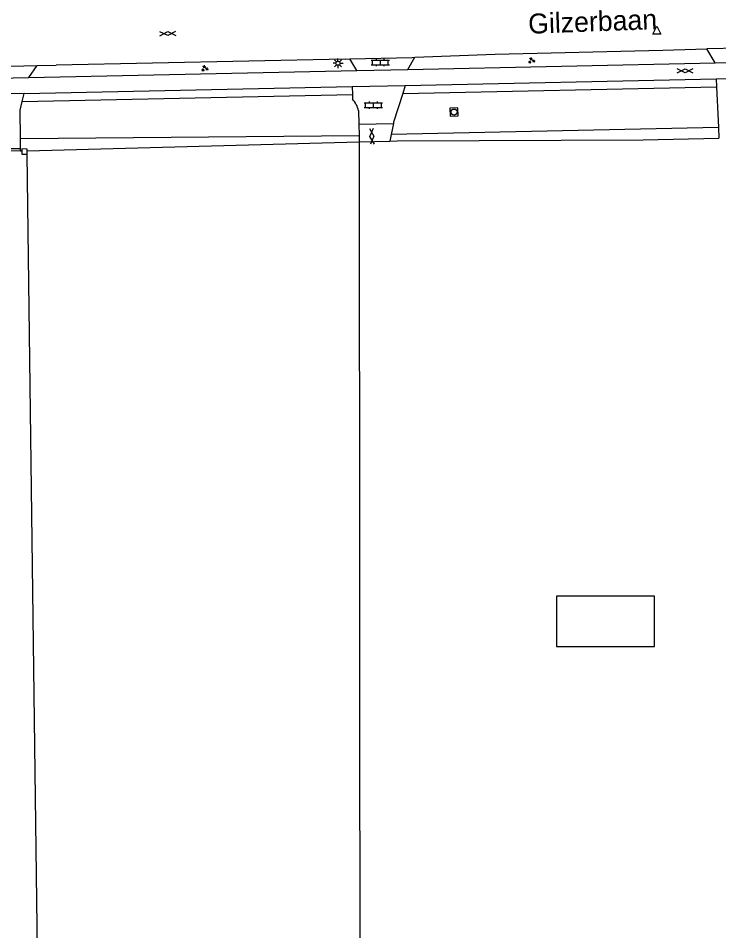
# Model space of a CAD drawing. Extents: x 128999 to 131010, y 395498 to 399007.
# Drawn here: x 130694.9 to 130782.7, y 396021.6 to 396136.1 of the extents above; entities that cross this region are included whole.
import ezdxf

# ---------------------------------------------------------------- set-up
doc = ezdxf.new("R2010")
doc.units = 0
for name, color, linetype in [('gg-afsc-erfafscheiding', 7, 'Continuous'), ('gg-afsc-hekwerk', 7, 'Continuous'), ('gg-afsc-muur', 7, 'Continuous'), ('gg-anno-openbare ruimte label', 7, 'Continuous'), ('gg-knt-verharding', 7, 'Continuous'), ('gt-bbg-plantopografie pand', 7, 'Continuous'), ('gt-grn-groengrens', 7, 'Continuous'), ('gt-grn-groengrens NZ', 7, 'Continuous'), ('gt-grn-vlakafsluiter', 7, 'Continuous'), ('gt-grn-weggrens', 7, 'Continuous'), ('gt-symb-gesloten verharding', 7, 'Continuous'), ('gt-symb-groenvak', 7, 'Continuous'), ('gt-symb-klinker verharding', 7, 'Continuous'), ('gt-symb-lichtmast', 7, 'Continuous'), ('gt-symb-rioolschacht', 7, 'Continuous'), ('gt-symb-waterafsluiter', 7, 'Continuous')]:
    doc.layers.add(name, color=color, linetype=linetype)

# ---------------------------------------------------------------- blocks, each defined once
blk = doc.blocks.new('gt0-GRVAK')
at = {"layer": 'gt-symb-groenvak'}
for p, q in [((-0.11, 0.19), (-0.23, 0.24)), ((-0.18, 0.15), (0.09, 0.15)), ((-0.09, 0.21), (-0.16, 0.32)), ((-0.05, 0.21), (-0.05, 0.39)), ((0, 0.21), (0.06, 0.32)), ((0.01, 0.19), (0.13, 0.24)), ((0.26, -0.05), (0.2, 0.06)), ((0.31, -0.05), (0.31, 0.13)), ((0.35, -0.05), (0.41, 0.06)), ((-0.24, -0.23), (-0.36, -0.18)), ((-0.32, -0.26), (-0.05, -0.26)), ((-0.23, -0.21), (-0.29, -0.1)), ((-0.18, -0.2), (-0.18, -0.02)), ((-0.14, -0.21), (-0.07, -0.1)), ((-0.12, -0.23), (0, -0.18)), ((0.24, -0.07), (0.12, -0.02)), ((0.17, -0.11), (0.44, -0.11)), ((0.37, -0.07), (0.49, -0.02))]:
    blk.add_line(p, q, dxfattribs=at)
blk = doc.blocks.new('gt0-WAFSL')
at = {"layer": 'gt-symb-waterafsluiter'}
for p, q in [((-0.5, -0.33), (0, 0.67)), ((0, 0.67), (0.5, -0.33)), ((0.5, -0.33), (-0.5, -0.33))]:
    blk.add_line(p, q, dxfattribs=at)
blk = doc.blocks.new('gt0-GESVH1')
at = {"layer": 'gt-symb-gesloten verharding'}
for p, q in [((-0.99, -0.26), (0.01, 0.24)), ((0.01, -0.26), (-0.99, 0.24)), ((0.01, 0.24), (1.01, -0.26)), ((1.01, 0.24), (0.01, -0.26))]:
    blk.add_line(p, q, dxfattribs=at)
blk = doc.blocks.new('gt0-KL1')
at = {"layer": 'gt-symb-klinker verharding'}
for p, q in [((-1.15, 0.3), (1.15, 0.3)), ((-1, -0.3), (-1, 0.3)), ((-0.5, 0.3), (-0.5, 0.45)), ((0, -0.3), (0, 0.3)), ((0.5, 0.3), (0.5, 0.45)), ((1, -0.3), (1, 0.3)), ((-1.15, -0.3), (1.15, -0.3)), ((-0.5, -0.45), (-0.5, -0.3)), ((0.5, -0.45), (0.5, -0.3))]:
    blk.add_line(p, q, dxfattribs=at)
blk = doc.blocks.new('gt0-RS')
at = {"layer": 'gt-symb-rioolschacht'}
blk.add_lwpolyline([(-0.5, -0.5), (0.5, -0.5), (0.5, 0.5), (-0.5, 0.5)], close=True, dxfattribs=at)
blk.add_circle((0, 0), 0.375, dxfattribs=at)
blk = doc.blocks.new('gt0-LMAST')
at = {"layer": 'gt-symb-lichtmast'}
for p, q in [((-0.18, 0.17), (-0.45, 0.44)), ((-0.01, 0.25), (-0.01, 0.62)), ((0.17, 0.17), (0.44, 0.44)), ((-0.26, 0), (-0.63, 0)), ((-0.18, -0.18), (-0.45, -0.45)), ((-0.01, -0.25), (-0.01, -0.63)), ((0.44, -0.45), (0.17, -0.18)), ((0.24, 0), (0.62, 0))]:
    blk.add_line(p, q, dxfattribs=at)
blk.add_circle((-0.01, 0), 0.25, dxfattribs=at)

msp = doc.modelspace()

# ---------------------------------------------------------------- linework, layer by layer
at = {"layer": 'gg-afsc-erfafscheiding'}
msp.add_lwpolyline([(130742.42, 396120.7), (130773.27, 396120.84), (130782.76, 396121.07)], dxfattribs=at)
at = {"layer": 'gg-afsc-hekwerk'}
for p, q in [((130691.73, 396119.52), (130695.18, 396119.47)), ((130695.18, 396119.47), (130695.36, 396119.47))]:
    msp.add_line(p, q, dxfattribs=at)
at = {"layer": 'gg-afsc-muur'}
msp.add_line((130696.01, 396119.03), (130696.03, 396119.48), dxfattribs=at)
for points in [[(130695.36, 396119.47), (130695.35, 396119.05), (130696.01, 396119.03)], [(130696.03, 396119.48), (130696.03, 396119.69), (130695.37, 396119.71), (130695.36, 396119.47)]]:
    msp.add_lwpolyline(points, dxfattribs=at)
at = {"layer": 'gg-knt-verharding'}
for p, q in [((130788.9, 396132.43), (130781.24, 396132.25)), ((130775.71, 396132.09), (130781.24, 396132.25)), ((130782.3, 396130.51), (130781.24, 396132.25)), ((130689.55, 396130), (130697.27, 396130.16)), ((130696.22, 396128.66), (130697.27, 396130.16)), ((130697.27, 396130.16), (130699.66, 396130.22)), ((130735.88, 396130.97), (130699.66, 396130.22)), ((130735.88, 396130.97), (130736.48, 396130.99)), ((130736.48, 396130.99), (130744.3, 396131.18)), ((130737.35, 396129.54), (130736.48, 396130.99)), ((130743.73, 396129.68), (130744.61, 396131.19)), ((130743.73, 396129.68), (130782.3, 396130.51)), ((130744.3, 396131.18), (130744.61, 396131.19)), ((130782.3, 396130.51), (130788.12, 396130.66)), ((130696.22, 396128.66), (130737.35, 396129.54)), ((130737.35, 396129.54), (130743.73, 396129.68)), ((130690.65, 396128.56), (130696.22, 396128.66)), ((130743.41, 396127.67), (130782.4, 396128.5)), ((130782.4, 396128.5), (130787.95, 396128.65)), ((130782.4, 396128.5), (130782.45, 396127.5)), ((130695.65, 396126.66), (130736.78, 396127.53)), ((130736.78, 396127.53), (130743.41, 396127.67)), ((130736.78, 396127.53), (130736.8, 396126.53)), ((130743.41, 396127.67), (130743.1, 396126.67)), ((130782.45, 396127.5), (130782.7, 396122.39)), ((130695.65, 396126.66), (130691.26, 396126.57)), ((130695.41, 396125.66), (130695.65, 396126.66)), ((130736.8, 396126.53), (130736.81, 396125.95)), ((130737.55, 396124.5), (130737.59, 396122.81)), ((130737.59, 396122.81), (130741.93, 396122.89)), ((130737.59, 396122.81), (130737.63, 396121.39)), ((130741.93, 396122.89), (130741.67, 396121.53)), ((130782.7, 396122.39), (130782.76, 396121.07)), ((130695.18, 396119.75), (130695.17, 396120.99)), ((130737.63, 396121.39), (130737.65, 396120.58)), ((130741.67, 396121.53), (130741.51, 396120.68)), ((130691.73, 396119.76), (130695.18, 396119.75)), ((130695.18, 396119.47), (130695.18, 396119.75))]:
    msp.add_line(p, q, dxfattribs=at)
for points in [[(130744.61, 396131.19), (130754.7, 396131.59), (130775.71, 396132.09)], [(130695.17, 396120.99), (130695.14, 396124.55), (130695.41, 396125.66)], [(130743.1, 396126.67), (130741.96, 396123.06), (130741.93, 396122.89)]]:
    msp.add_lwpolyline(points, dxfattribs=at)
msp.add_arc((130734.65, 396123.93), 2.96, 11.0059, 43.066, dxfattribs=at)
at = {"layer": 'gt-bbg-plantopografie pand'}
msp.add_lwpolyline([(130762.38, 396057.27), (130774.69, 396057.27), (130774.69, 396063.6), (130762.38, 396063.6), (130762.38, 396057.27)], dxfattribs=at)
at = {"layer": 'gt-grn-groengrens'}
for p, q in [((130782.7, 396122.39), (130741.67, 396121.53)), ((130695.17, 396120.99), (130737.63, 396121.39)), ((130696.03, 396119.48), (130737.65, 396120.58))]:
    msp.add_line(p, q, dxfattribs=at)
at = {"layer": 'gt-grn-groengrens NZ'}
for p, q in [((130743.1, 396126.67), (130782.45, 396127.5)), ((130695.41, 396125.66), (130736.8, 396126.53))]:
    msp.add_line(p, q, dxfattribs=at)
at = {"layer": 'gt-grn-vlakafsluiter'}
for p, q in [((130741.51, 396120.68), (130742.42, 396120.7)), ((130697.55, 396001.07), (130696.01, 396119.03))]:
    msp.add_line(p, q, dxfattribs=at)
msp.add_lwpolyline([(130737.65, 396120.58), (130737.74, 396005.41), (130722.63, 396000.15), (130697.55, 396001.07)], dxfattribs=at)
at = {"layer": 'gt-grn-weggrens'}
msp.add_line((130737.65, 396120.58), (130741.51, 396120.68), dxfattribs=at)

# ---------------------------------------------------------------- block references
at = {"layer": 'gt-symb-gesloten verharding'}
for p, rotation in [((130713.63, 396134.17), 1.3175706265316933), ((130739.26, 396121.3), -87.30638896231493)]:
    msp.add_blockref('gt0-GESVH1', p, dxfattribs=dict(at, rotation=rotation))
msp.add_blockref('gt0-GESVH1', (130778.49, 396129.51), dxfattribs=at)
at = {"layer": 'gt-symb-groenvak', "rotation": -2.9796737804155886}
for p in [(130718.27, 396129.8), (130759.24, 396130.77)]:
    msp.add_blockref('gt0-GRVAK', p, dxfattribs=at)
at = {"layer": 'gt-symb-klinker verharding'}
for p in [(130740.3, 396130.54), (130739.44, 396125.19)]:
    msp.add_blockref('gt0-KL1', p, dxfattribs=at)
at = {"layer": 'gt-symb-lichtmast'}
msp.add_blockref('gt0-LMAST', (130735, 396130.44), dxfattribs=at)
at = {"layer": 'gt-symb-rioolschacht', "rotation": 1.203034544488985}
msp.add_blockref('gt0-RS', (130749.54, 396124.33), dxfattribs=at)
at = {"layer": 'gt-symb-waterafsluiter'}
msp.add_blockref('gt0-WAFSL', (130774.98, 396134.41), dxfattribs=at)

# ---------------------------------------------------------------- texts
at = {"layer": 'gg-anno-openbare ruimte label'}
msp.add_text('Gilzerbaan', height=2.5, rotation=2.1, dxfattribs=at).set_placement((130758.88, 396134.14))

doc.saveas('drawing.dxf')
